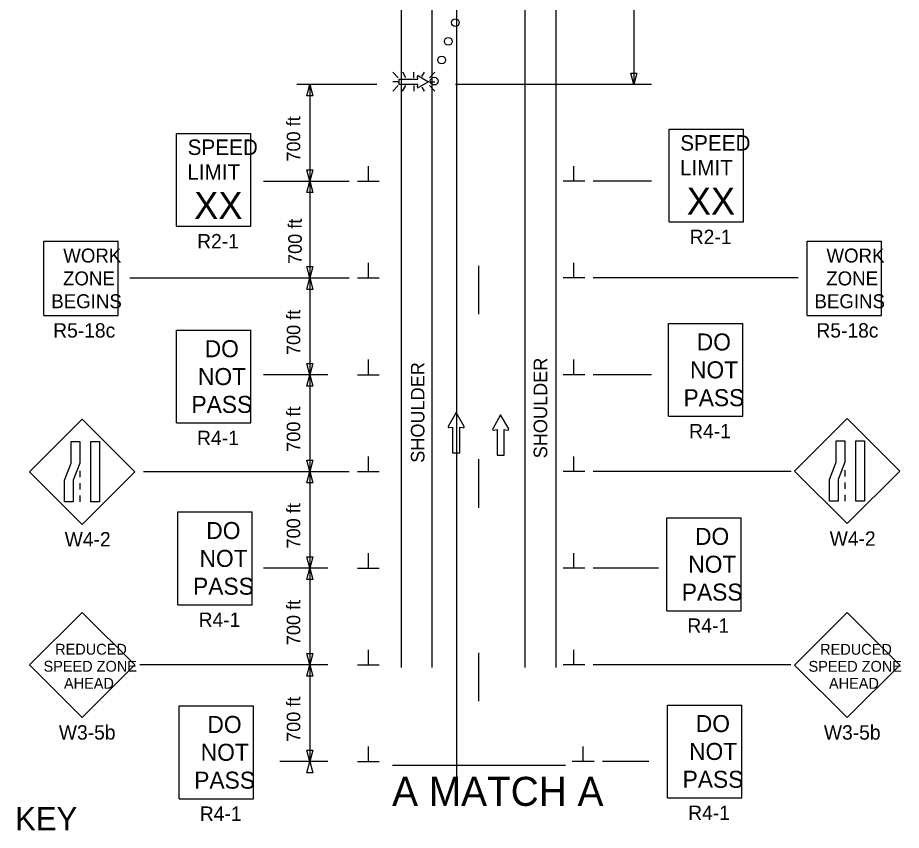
# Model space of a CAD drawing. Extents: x 15278 to 18126, y 1908 to 6555.
# Drawn here: x 15354.9 to 15811.5, y 2392.6 to 2812.7 of the extents above; entities that cross this region are included whole.
import ezdxf

# ---------------------------------------------------------------- set-up
doc = ezdxf.new("R2010")
doc.units = 0
for name, color, linetype in [('ALI_LEGAL_EX', 7, 'Continuous'), ('MT_SCRATCH_LEVEL_E', 7, 'Continuous'), ('PAVT_EDGE_EX', 7, 'Continuous'), ('TRAFFIC_SIGNS_PR', 7, 'Continuous'), ('TYPICAL_TEXT_DIMEN_EX', 7, 'Continuous'), ('TYPICAL_TEXT_DIMEN_PR', 7, 'Continuous')]:
    doc.layers.add(name, color=color, linetype=linetype)

msp = doc.modelspace()

# ---------------------------------------------------------------- linework, layer by layer
at = {"layer": 'ALI_LEGAL_EX'}
msp.add_line((15581.68, 3237.79), (15581.68, 2408.6), dxfattribs=at)
for points in [[(15593, 2684.34), (15593, 2659.34)], [(15593, 2584.34), (15593, 2559.34)], [(15593, 2484.34), (15593, 2459.34)]]:
    msp.add_lwpolyline(points, dxfattribs=at)
at = {"layer": 'MT_SCRATCH_LEVEL_E'}
for p, q in [((15581.51, 2608.63), (15577.39, 2601.39)), ((15585.65, 2601.39), (15581.51, 2608.63)), ((15604.48, 2607.36), (15600.37, 2600.12)), ((15608.63, 2600.12), (15604.48, 2607.36)), ((15577.88, 2600.71), (15579.65, 2601.02)), ((15579.65, 2601.02), (15579.65, 2587.77)), ((15583.4, 2587.77), (15583.4, 2601.02)), ((15583.4, 2601.02), (15585.17, 2600.71)), ((15600.85, 2599.44), (15602.63, 2599.75)), ((15602.63, 2599.75), (15602.63, 2586.5)), ((15606.37, 2586.5), (15606.37, 2599.75)), ((15606.37, 2599.75), (15608.15, 2599.44)), ((15579.65, 2587.77), (15583.4, 2587.77)), ((15602.63, 2586.5), (15606.37, 2586.5))]:
    msp.add_line(p, q, dxfattribs=at)
for centre, start, end in [((15577.8, 2601.17), 150.4248, 279.9638), ((15585.24, 2601.17), 260.0362, 29.7731), ((15600.78, 2599.9), 150.4248, 279.9638), ((15608.22, 2599.9), 260.0362, 29.7731)]:
    msp.add_arc(centre, 0.463, start, end, dxfattribs=at)
at = {"layer": 'PAVT_EDGE_EX'}
for p, q in [((15553, 3162.29), (15553, 2476.81)), ((15569, 3162.29), (15569, 2476.81)), ((15617, 3162.29), (15617, 2476.81)), ((15633, 3163.21), (15633, 2476.81))]:
    msp.add_line(p, q, dxfattribs=at)
at = {"layer": 'TRAFFIC_SIGNS_PR'}
for p, q in [((15551.53, 2781.59), (15548.71, 2784.41)), ((15555.48, 2781.59), (15553.85, 2784.41)), ((15559.62, 2781.59), (15559.62, 2784.41)), ((15563.8, 2782.22), (15565.06, 2784.41)), ((15570.52, 2784.4), (15567.7, 2781.59)), ((15551.53, 2779.55), (15548.71, 2779.55)), ((15551.53, 2777.52), (15548.71, 2774.7)), ((15553.83, 2774.7), (15555.46, 2777.52)), ((15559.62, 2777.52), (15559.62, 2774.7)), ((15565.09, 2774.7), (15563.88, 2776.79)), ((15567.7, 2779.55), (15570.52, 2779.55)), ((15570.52, 2774.7), (15567.7, 2777.52)), ((15691.54, 2755.05), (15729.94, 2755.05)), ((15691.54, 2707.05), (15691.54, 2755.05)), ((15729.94, 2707.05), (15729.94, 2755.05)), ((15436.95, 2752.82), (15475.35, 2752.82)), ((15436.95, 2704.82), (15436.95, 2752.82)), ((15475.35, 2704.82), (15475.35, 2752.82)), ((15436.95, 2704.82), (15475.35, 2704.82)), ((15691.54, 2707.05), (15729.94, 2707.05)), ((15368.42, 2658.71), (15368.42, 2697.11)), ((15368.42, 2697.11), (15406.82, 2697.11)), ((15406.82, 2658.71), (15406.82, 2697.11)), ((15762.84, 2658.71), (15762.84, 2697.11)), ((15762.84, 2697.11), (15801.24, 2697.11)), ((15801.24, 2658.71), (15801.24, 2697.11)), ((15368.42, 2658.71), (15406.82, 2658.71)), ((15762.84, 2658.71), (15801.24, 2658.71)), ((15691.19, 2606.6), (15691.19, 2654.6)), ((15691.19, 2654.6), (15729.59, 2654.6)), ((15729.59, 2606.6), (15729.59, 2654.6)), ((15436.91, 2603.13), (15436.91, 2651.13)), ((15436.91, 2651.13), (15475.31, 2651.13)), ((15475.31, 2603.13), (15475.31, 2651.13)), ((15388.21, 2605.03), (15361.06, 2577.88)), ((15415.36, 2577.88), (15388.21, 2605.03)), ((15436.91, 2603.13), (15475.31, 2603.13)), ((15691.19, 2606.6), (15729.59, 2606.6)), ((15783.56, 2605.39), (15756.41, 2578.24)), ((15810.72, 2578.24), (15783.56, 2605.39)), ((15361.06, 2577.88), (15388.21, 2550.73)), ((15386.96, 2578.37), (15386.96, 2575.17)), ((15388.21, 2550.73), (15415.36, 2577.88)), ((15756.41, 2578.24), (15783.56, 2551.09)), ((15782.32, 2578.73), (15782.32, 2575.53)), ((15783.56, 2551.09), (15810.72, 2578.24)), ((15386.96, 2571.97), (15386.96, 2568.77)), ((15782.32, 2572.33), (15782.32, 2569.13)), ((15386.96, 2565.57), (15386.96, 2562.37)), ((15782.32, 2565.93), (15782.32, 2562.73)), ((15437.72, 2509.14), (15437.72, 2557.14)), ((15437.72, 2557.14), (15476.12, 2557.14)), ((15476.12, 2509.14), (15476.12, 2557.14)), ((15690.3, 2506.1), (15690.3, 2554.1)), ((15690.3, 2554.1), (15728.7, 2554.1)), ((15728.7, 2506.1), (15728.7, 2554.1)), ((15437.72, 2509.14), (15476.12, 2509.14)), ((15388.2, 2505.22), (15361.05, 2478.06)), ((15415.35, 2478.06), (15388.2, 2505.22)), ((15690.3, 2506.1), (15728.7, 2506.1)), ((15783.55, 2505.18), (15756.4, 2478.02)), ((15810.71, 2478.02), (15783.55, 2505.18)), ((15361.05, 2478.06), (15388.2, 2450.91)), ((15388.2, 2450.91), (15415.35, 2478.06)), ((15756.4, 2478.02), (15783.55, 2450.87)), ((15783.55, 2450.87), (15810.71, 2478.02)), ((15438.33, 2408.89), (15438.33, 2456.89)), ((15438.33, 2456.89), (15476.73, 2456.89)), ((15476.73, 2408.89), (15476.73, 2456.89)), ((15690.72, 2409.34), (15690.72, 2457.34)), ((15690.72, 2457.34), (15729.12, 2457.34)), ((15729.12, 2409.34), (15729.12, 2457.34)), ((15438.33, 2408.89), (15476.73, 2408.89)), ((15690.72, 2409.34), (15729.12, 2409.34))]:
    msp.add_line(p, q, dxfattribs=at)
for points in [[(15561.44, 2776.87), (15561.67, 2778.17), (15551.95, 2778.17), (15551.95, 2780.91), (15561.67, 2780.91), (15561.44, 2782.21)], [(15561.94, 2782.57), (15567.25, 2779.55), (15561.94, 2776.51)]]:
    msp.add_lwpolyline(points, dxfattribs=at)
for points in [[(15782.32, 2593.98), (15782.32, 2582.8), (15778.97, 2573.91), (15778.97, 2562.73), (15774.48, 2562.73), (15774.48, 2573.91), (15777.82, 2582.8), (15777.82, 2593.98)], [(15792.45, 2593.98), (15792.45, 2562.73), (15787.96, 2562.73), (15787.96, 2593.98)], [(15386.96, 2593.62), (15386.96, 2582.44), (15383.62, 2573.55), (15383.62, 2562.37), (15379.12, 2562.37), (15379.12, 2573.55), (15382.47, 2582.44), (15382.47, 2593.62)], [(15397.1, 2593.62), (15397.1, 2562.37), (15392.61, 2562.37), (15392.61, 2593.62)]]:
    msp.add_lwpolyline(points, close=True, dxfattribs=at)
for centre in [(15581.11, 2810.1), (15577.45, 2800.42), (15573.97, 2790.75), (15570.12, 2779.86)]:
    msp.add_circle(centre, 2, dxfattribs=at)
for centre, start, end in [((15561.78, 2782.27), 61.1084, 189.2692), ((15561.78, 2776.81), 170.0407, 298.5167)]:
    msp.add_arc(centre, 0.341, start, end, dxfattribs=at)
at = {"layer": 'TYPICAL_TEXT_DIMEN_PR'}
for p, q in [((15673.27, 2847.05), (15673.27, 2778.09)), ((15673.25, 2778.08), (15671.68, 2783.95)), ((15671.68, 2783.95), (15673.25, 2783.95)), ((15673.25, 2783.95), (15674.82, 2783.95)), ((15674.82, 2783.95), (15673.25, 2778.08)), ((15540.45, 2778.08), (15499.13, 2778.08)), ((15504.31, 2772.22), (15505.88, 2778.08)), ((15505.88, 2778.08), (15505.88, 2728.08)), ((15505.88, 2778.08), (15507.45, 2772.22)), ((15682.48, 2778.08), (15581.07, 2778.08)), ((15505.88, 2772.22), (15504.31, 2772.22)), ((15507.45, 2772.22), (15505.88, 2772.22)), ((15536.12, 2728.08), (15536.12, 2735.87)), ((15642.37, 2728.08), (15642.37, 2735.87)), ((15505.88, 2728.08), (15504.31, 2733.95)), ((15504.31, 2733.95), (15505.88, 2733.95)), ((15505.88, 2733.95), (15507.45, 2733.95)), ((15507.45, 2733.95), (15505.88, 2728.08)), ((15482, 2728.08), (15526.25, 2728.08)), ((15504.31, 2722.22), (15505.88, 2728.08)), ((15504.31, 2722.22), (15505.88, 2728.08)), ((15505.88, 2728.08), (15505.88, 2678.08)), ((15505.88, 2728.08), (15507.45, 2722.22)), ((15505.88, 2728.08), (15507.45, 2722.22)), ((15530.5, 2728.08), (15541.75, 2728.08)), ((15648, 2728.08), (15636.75, 2728.08)), ((15682.48, 2728.08), (15652.25, 2728.08)), ((15505.88, 2722.22), (15504.31, 2722.22)), ((15505.88, 2722.22), (15504.31, 2722.22)), ((15507.45, 2722.22), (15505.88, 2722.22)), ((15507.45, 2722.22), (15505.88, 2722.22)), ((15536.12, 2678.08), (15536.12, 2685.87)), ((15642.37, 2678.08), (15642.37, 2685.87)), ((15505.88, 2678.08), (15504.31, 2683.95)), ((15504.31, 2683.95), (15505.88, 2683.95)), ((15505.88, 2678.08), (15504.31, 2683.95)), ((15504.31, 2683.95), (15505.88, 2683.95)), ((15505.88, 2683.95), (15507.45, 2683.95)), ((15507.45, 2683.95), (15505.88, 2678.08)), ((15505.88, 2683.95), (15507.45, 2683.95)), ((15507.45, 2683.95), (15505.88, 2678.08)), ((15412.92, 2678.08), (15526.25, 2678.08)), ((15504.31, 2672.22), (15505.88, 2678.08)), ((15505.88, 2678.08), (15505.88, 2628.08)), ((15505.88, 2678.08), (15507.45, 2672.22)), ((15530.5, 2678.08), (15541.75, 2678.08)), ((15648, 2678.08), (15636.75, 2678.08)), ((15758.21, 2678.08), (15652.25, 2678.08)), ((15505.88, 2672.22), (15504.31, 2672.22)), ((15507.45, 2672.22), (15505.88, 2672.22)), ((15536.12, 2628.08), (15536.12, 2635.87)), ((15642.37, 2628.08), (15642.37, 2635.87)), ((15505.88, 2628.08), (15504.31, 2633.95)), ((15504.31, 2633.95), (15505.88, 2633.95)), ((15505.88, 2633.95), (15507.45, 2633.95)), ((15507.45, 2633.95), (15505.88, 2628.08)), ((15515.11, 2628.08), (15482, 2628.08)), ((15504.31, 2622.22), (15505.88, 2628.08)), ((15505.88, 2628.08), (15505.88, 2578.08)), ((15505.88, 2628.08), (15507.45, 2622.22)), ((15530.5, 2628.08), (15541.75, 2628.08)), ((15648, 2628.08), (15636.75, 2628.08)), ((15682.48, 2628.08), (15652.25, 2628.08)), ((15505.88, 2622.22), (15504.31, 2622.22)), ((15507.45, 2622.22), (15505.88, 2622.22)), ((15536.12, 2578.08), (15536.12, 2585.87)), ((15642.37, 2578.08), (15642.37, 2585.87)), ((15505.88, 2578.08), (15504.31, 2583.95)), ((15504.31, 2583.95), (15505.88, 2583.95)), ((15505.88, 2578.08), (15504.31, 2583.95)), ((15504.31, 2583.95), (15505.88, 2583.95)), ((15505.88, 2583.95), (15507.45, 2583.95)), ((15507.45, 2583.95), (15505.88, 2578.08)), ((15505.88, 2583.95), (15507.45, 2583.95)), ((15507.45, 2583.95), (15505.88, 2578.08)), ((15419.97, 2578.08), (15526.25, 2578.08)), ((15504.31, 2572.22), (15505.88, 2578.08)), ((15505.88, 2578.08), (15505.88, 2528.08)), ((15505.88, 2578.08), (15507.45, 2572.22)), ((15530.5, 2578.08), (15541.75, 2578.08)), ((15648, 2578.08), (15636.75, 2578.08)), ((15754.63, 2578.08), (15652.25, 2578.08)), ((15505.88, 2572.22), (15504.31, 2572.22)), ((15507.45, 2572.22), (15505.88, 2572.22)), ((15536.12, 2528.08), (15536.12, 2535.87)), ((15642.37, 2528.08), (15642.37, 2535.87)), ((15505.88, 2528.08), (15504.31, 2533.95)), ((15504.31, 2533.95), (15505.88, 2533.95)), ((15505.88, 2533.95), (15507.45, 2533.95)), ((15507.45, 2533.95), (15505.88, 2528.08)), ((15515.11, 2528.08), (15482, 2528.08)), ((15504.31, 2522.22), (15505.88, 2528.08)), ((15505.88, 2528.08), (15507.45, 2522.22)), ((15505.88, 2528.08), (15505.88, 2478.08)), ((15530.5, 2528.08), (15541.75, 2528.08)), ((15648, 2528.08), (15636.75, 2528.08)), ((15686.13, 2528.08), (15652.25, 2528.08)), ((15505.88, 2522.22), (15504.31, 2522.22)), ((15507.45, 2522.22), (15505.88, 2522.22)), ((15536.12, 2478.08), (15536.12, 2485.87)), ((15642.37, 2478.08), (15642.37, 2485.87)), ((15505.88, 2478.08), (15504.31, 2483.95)), ((15504.31, 2483.95), (15505.88, 2483.95)), ((15505.88, 2483.95), (15507.45, 2483.95)), ((15507.45, 2483.95), (15505.88, 2478.08)), ((15515.11, 2478.08), (15417.98, 2478.08)), ((15504.31, 2472.22), (15505.88, 2478.08)), ((15505.88, 2478.08), (15507.45, 2472.22)), ((15505.88, 2478.08), (15505.88, 2428.08)), ((15530.5, 2478.08), (15541.75, 2478.08)), ((15648, 2478.08), (15636.75, 2478.08)), ((15754.41, 2478.08), (15652.25, 2478.08)), ((15505.88, 2472.22), (15504.31, 2472.22)), ((15507.45, 2472.22), (15505.88, 2472.22)), ((15536.12, 2428.08), (15536.12, 2435.87)), ((15647.13, 2428.08), (15647.13, 2435.87)), ((15505.88, 2428.08), (15504.31, 2433.95)), ((15504.31, 2433.95), (15505.88, 2433.95)), ((15505.88, 2433.95), (15507.45, 2433.95)), ((15507.45, 2433.95), (15505.88, 2428.08)), ((15515.11, 2428.08), (15490.34, 2428.08)), ((15504.31, 2422.22), (15505.88, 2428.08)), ((15505.88, 2428.08), (15507.45, 2422.22)), ((15530.5, 2428.08), (15541.75, 2428.08)), ((15637.95, 2426.15), (15548.53, 2426.15)), ((15652.75, 2428.08), (15641.5, 2428.08)), ((15681.12, 2428.08), (15657.07, 2428.08)), ((15505.88, 2422.22), (15504.31, 2422.22)), ((15507.45, 2422.22), (15505.88, 2422.22))]:
    msp.add_line(p, q, dxfattribs=at)

# ---------------------------------------------------------------- texts
at = {"layer": 'TRAFFIC_SIGNS_PR'}
for s, height, p in [('SPEED', 8, (15442.72, 2741.68)), ('SPEED', 8, (15697.31, 2743.92)), ('LIMIT', 8, (15442.56, 2728.88)), ('LIMIT', 8, (15697.14, 2731.12)), ('XX', 14.031, (15446.06, 2708.58)), ('XX', 14.031, (15700.65, 2710.81)), ('R2-1', 7.44, (15447.63, 2693.38)), ('R2-1', 7.44, (15702.21, 2695.61)), ('WORK', 7.217, (15378.42, 2686.08)), ('WORK', 7.217, (15772.84, 2686.08)), ('ZONE', 7.217, (15378.3, 2674.27)), ('ZONE', 7.217, (15772.72, 2674.27)), ('BEGINS', 7.217, (15372.23, 2662.46)), ('BEGINS', 7.217, (15766.65, 2662.46)), ('R5-18c', 7.44, (15373.23, 2647.27)), ('R5-18c', 7.44, (15767.65, 2647.27)), ('DO', 8.8, (15705.83, 2640.61)), ('DO', 8.8, (15451.54, 2637.13)), ('NOT', 8.8, (15702.34, 2626.21)), ('NOT', 8.8, (15448.05, 2622.73)), ('PASS', 8.8, (15444.7, 2608.33)), ('PASS', 8.8, (15698.99, 2611.81)), ('R4-1', 7.44, (15447.59, 2591.69)), ('R4-1', 7.44, (15701.87, 2595.17)), ('DO', 8.8, (15452.36, 2543.14)), ('DO', 8.8, (15704.94, 2540.11)), ('W4-2', 7.44, (15379.17, 2539.29)), ('W4-2', 7.44, (15774.52, 2539.65)), ('NOT', 8.8, (15448.87, 2528.74)), ('NOT', 8.8, (15701.45, 2525.71)), ('PASS', 8.8, (15445.52, 2514.34)), ('PASS', 8.8, (15698.1, 2511.31)), ('R4-1', 7.44, (15448.4, 2497.7)), ('R4-1', 7.44, (15700.98, 2494.67)), ('REDUCED', 5.6, (15374.26, 2483.37)), ('REDUCED', 5.6, (15769.61, 2483.33)), ('SPEED ZONE', 5.6, (15368.25, 2474.57)), ('SPEED ZONE', 5.6, (15763.6, 2474.53)), ('AHEAD', 5.6, (15378.81, 2465.77)), ('AHEAD', 5.6, (15774.16, 2465.73)), ('DO', 8.8, (15452.96, 2442.89)), ('DO', 8.8, (15705.35, 2443.34)), ('W3-5b', 7.44, (15376.15, 2439.47)), ('W3-5b', 7.44, (15771.51, 2439.43)), ('NOT', 8.8, (15449.48, 2428.49)), ('NOT', 8.8, (15701.87, 2428.94)), ('PASS', 8.8, (15446.13, 2414.09)), ('PASS', 8.8, (15698.52, 2414.54)), ('R4-1', 7.44, (15449.01, 2397.45)), ('R4-1', 7.44, (15701.4, 2397.9))]:
    msp.add_text(s, height=height, dxfattribs=at).set_placement(p)
at = {"layer": 'TYPICAL_TEXT_DIMEN_EX'}
msp.add_text('KEY', height=12, dxfattribs=at).set_placement((15353.56, 2392.55))
at = {"layer": 'TYPICAL_TEXT_DIMEN_PR'}
for s, p in [('700 ft', (15500.92, 2738.25)), ('700 ft', (15501.7, 2685.32)), ('700 ft', (15500.92, 2638.25)), ('SHOULDER', (15628.53, 2584.88)), ('SHOULDER', (15565.1, 2582.57)), ('700 ft', (15500.92, 2588.25)), ('700 ft', (15500.92, 2538.25)), ('700 ft', (15500.92, 2488.25)), ('700 ft', (15500.92, 2438.25))]:
    msp.add_text(s, height=7, rotation=90, dxfattribs=at).set_placement(p)
msp.add_text('A MATCH A', height=15, dxfattribs=at).set_placement((15548.39, 2405.21))

doc.saveas('drawing.dxf')
